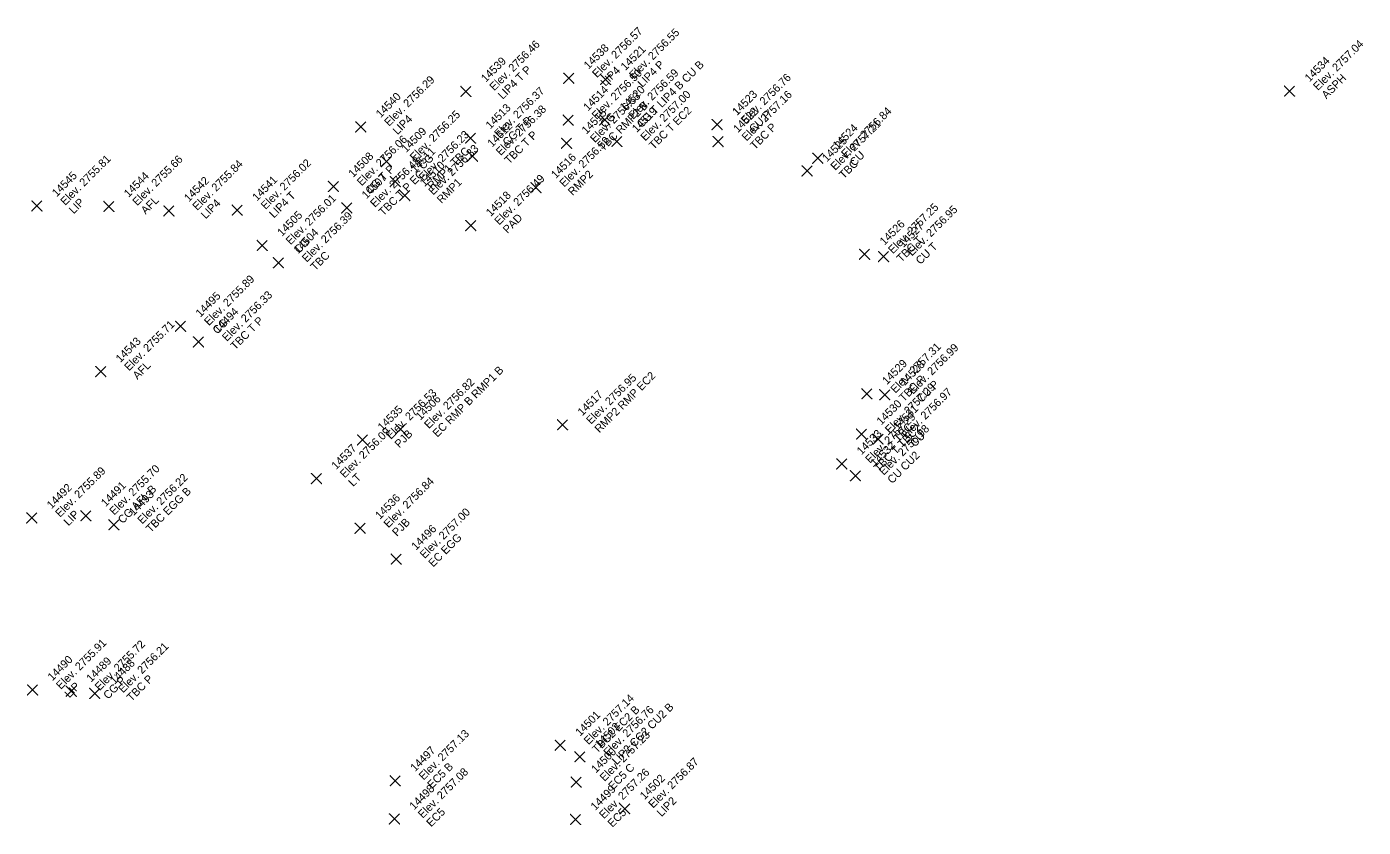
# Model space of a CAD drawing. Extents: x 2493999 to 2503109, y 700767 to 706646.
# Drawn here: x 2502322.22 to 2502362.3, y 703506.66 to 703530.66 of the extents above; entities that cross this region are included whole.
import ezdxf

# ---------------------------------------------------------------- set-up
doc = ezdxf.new("R2010")
doc.units = 0
doc.layers.add('ALG_CL_BLUE_Horiz', color=7, linetype='Continuous')
doc.layers.add('DES_SURFACE_Existing-Ground', color=7, linetype='Continuous')

msp = doc.modelspace()

# ---------------------------------------------------------------- linework, layer by layer
at = {"layer": 'ALG_CL_BLUE_Horiz'}
for points in [[(2502335.391, 703528.719), (2502335.241, 703528.869), (2502335.391, 703528.719), (2502335.241, 703528.569), (2502335.391, 703528.719), (2502335.541, 703528.569), (2502335.391, 703528.719), (2502335.541, 703528.869)], [(2502338.472, 703529.111), (2502338.322, 703529.261), (2502338.472, 703529.111), (2502338.322, 703528.961), (2502338.472, 703529.111), (2502338.622, 703528.961), (2502338.472, 703529.111), (2502338.622, 703529.261)], [(2502339.578, 703529.076), (2502339.428, 703529.226), (2502339.578, 703529.076), (2502339.428, 703528.926), (2502339.578, 703529.076), (2502339.728, 703528.926), (2502339.578, 703529.076), (2502339.728, 703529.226)], [(2502360.093, 703528.73), (2502359.943, 703528.88), (2502360.093, 703528.73), (2502359.943, 703528.58), (2502360.093, 703528.73), (2502360.243, 703528.58), (2502360.093, 703528.73), (2502360.243, 703528.88)], [(2502332.236, 703527.655), (2502332.086, 703527.805), (2502332.236, 703527.655), (2502332.086, 703527.505), (2502332.236, 703527.655), (2502332.386, 703527.505), (2502332.236, 703527.655), (2502332.386, 703527.805)], [(2502338.458, 703527.858), (2502338.308, 703528.008), (2502338.458, 703527.858), (2502338.308, 703527.708), (2502338.458, 703527.858), (2502338.608, 703527.708), (2502338.458, 703527.858), (2502338.608, 703528.008)], [(2502339.554, 703527.863), (2502339.404, 703528.013), (2502339.554, 703527.863), (2502339.404, 703527.713), (2502339.554, 703527.863), (2502339.704, 703527.713), (2502339.554, 703527.863), (2502339.704, 703528.013)], [(2502342.924, 703527.723), (2502342.774, 703527.873), (2502342.924, 703527.723), (2502342.774, 703527.573), (2502342.924, 703527.723), (2502343.074, 703527.573), (2502342.924, 703527.723), (2502343.074, 703527.873)], [(2502335.53, 703527.318), (2502335.38, 703527.468), (2502335.53, 703527.318), (2502335.38, 703527.168), (2502335.53, 703527.318), (2502335.68, 703527.168), (2502335.53, 703527.318), (2502335.68, 703527.468)], [(2502338.408, 703527.166), (2502338.258, 703527.316), (2502338.408, 703527.166), (2502338.258, 703527.016), (2502338.408, 703527.166), (2502338.558, 703527.016), (2502338.408, 703527.166), (2502338.558, 703527.316)], [(2502339.918, 703527.217), (2502339.768, 703527.367), (2502339.918, 703527.217), (2502339.768, 703527.067), (2502339.918, 703527.217), (2502340.068, 703527.067), (2502339.918, 703527.217), (2502340.068, 703527.367)], [(2502342.953, 703527.212), (2502342.803, 703527.362), (2502342.953, 703527.212), (2502342.803, 703527.062), (2502342.953, 703527.212), (2502343.103, 703527.062), (2502342.953, 703527.212), (2502343.103, 703527.362)], [(2502335.584, 703526.775), (2502335.434, 703526.925), (2502335.584, 703526.775), (2502335.434, 703526.625), (2502335.584, 703526.775), (2502335.734, 703526.625), (2502335.584, 703526.775), (2502335.734, 703526.925)], [(2502345.939, 703526.713), (2502345.789, 703526.863), (2502345.939, 703526.713), (2502345.789, 703526.563), (2502345.939, 703526.713), (2502346.089, 703526.563), (2502345.939, 703526.713), (2502346.089, 703526.863)], [(2502333.004, 703526.614), (2502332.854, 703526.764), (2502333.004, 703526.614), (2502332.854, 703526.464), (2502333.004, 703526.614), (2502333.154, 703526.464), (2502333.004, 703526.614), (2502333.154, 703526.764)], [(2502345.619, 703526.334), (2502345.469, 703526.484), (2502345.619, 703526.334), (2502345.469, 703526.184), (2502345.619, 703526.334), (2502345.769, 703526.184), (2502345.619, 703526.334), (2502345.769, 703526.484)], [(2502333.272, 703526.012), (2502333.122, 703526.162), (2502333.272, 703526.012), (2502333.122, 703525.862), (2502333.272, 703526.012), (2502333.422, 703525.862), (2502333.272, 703526.012), (2502333.422, 703526.162)], [(2502331.414, 703525.868), (2502331.264, 703526.018), (2502331.414, 703525.868), (2502331.264, 703525.718), (2502331.414, 703525.868), (2502331.564, 703525.718), (2502331.414, 703525.868), (2502331.564, 703526.018)], [(2502333.556, 703525.594), (2502333.406, 703525.744), (2502333.556, 703525.594), (2502333.406, 703525.444), (2502333.556, 703525.594), (2502333.706, 703525.444), (2502333.556, 703525.594), (2502333.706, 703525.744)], [(2502337.491, 703525.833), (2502337.341, 703525.983), (2502337.491, 703525.833), (2502337.341, 703525.683), (2502337.491, 703525.833), (2502337.641, 703525.683), (2502337.491, 703525.833), (2502337.641, 703525.983)], [(2502322.523, 703525.285), (2502322.373, 703525.435), (2502322.523, 703525.285), (2502322.373, 703525.135), (2502322.523, 703525.285), (2502322.673, 703525.135), (2502322.523, 703525.285), (2502322.673, 703525.435)], [(2502324.682, 703525.272), (2502324.532, 703525.422), (2502324.682, 703525.272), (2502324.532, 703525.122), (2502324.682, 703525.272), (2502324.832, 703525.122), (2502324.682, 703525.272), (2502324.832, 703525.422)], [(2502326.485, 703525.133), (2502326.335, 703525.283), (2502326.485, 703525.133), (2502326.335, 703524.983), (2502326.485, 703525.133), (2502326.635, 703524.983), (2502326.485, 703525.133), (2502326.635, 703525.283)], [(2502328.532, 703525.159), (2502328.382, 703525.309), (2502328.532, 703525.159), (2502328.382, 703525.009), (2502328.532, 703525.159), (2502328.682, 703525.009), (2502328.532, 703525.159), (2502328.682, 703525.309)], [(2502331.814, 703525.224), (2502331.664, 703525.374), (2502331.814, 703525.224), (2502331.664, 703525.074), (2502331.814, 703525.224), (2502331.964, 703525.074), (2502331.814, 703525.224), (2502331.964, 703525.374)], [(2502335.537, 703524.696), (2502335.387, 703524.846), (2502335.537, 703524.696), (2502335.387, 703524.546), (2502335.537, 703524.696), (2502335.687, 703524.546), (2502335.537, 703524.696), (2502335.687, 703524.846)], [(2502329.282, 703524.101), (2502329.132, 703524.251), (2502329.282, 703524.101), (2502329.132, 703523.951), (2502329.282, 703524.101), (2502329.432, 703523.951), (2502329.282, 703524.101), (2502329.432, 703524.251)], [(2502329.767, 703523.579), (2502329.617, 703523.729), (2502329.767, 703523.579), (2502329.617, 703523.429), (2502329.767, 703523.579), (2502329.917, 703523.429), (2502329.767, 703523.579), (2502329.917, 703523.729)], [(2502347.348, 703523.834), (2502347.198, 703523.984), (2502347.348, 703523.834), (2502347.198, 703523.684), (2502347.348, 703523.834), (2502347.498, 703523.684), (2502347.348, 703523.834), (2502347.498, 703523.984)], [(2502347.917, 703523.767), (2502347.767, 703523.917), (2502347.917, 703523.767), (2502347.767, 703523.617), (2502347.917, 703523.767), (2502348.067, 703523.617), (2502347.917, 703523.767), (2502348.067, 703523.917)], [(2502326.832, 703521.679), (2502326.682, 703521.829), (2502326.832, 703521.679), (2502326.682, 703521.529), (2502326.832, 703521.679), (2502326.982, 703521.529), (2502326.832, 703521.679), (2502326.982, 703521.829)], [(2502327.368, 703521.206), (2502327.218, 703521.356), (2502327.368, 703521.206), (2502327.218, 703521.056), (2502327.368, 703521.206), (2502327.518, 703521.056), (2502327.368, 703521.206), (2502327.518, 703521.356)], [(2502324.437, 703520.319), (2502324.287, 703520.469), (2502324.437, 703520.319), (2502324.287, 703520.169), (2502324.437, 703520.319), (2502324.587, 703520.169), (2502324.437, 703520.319), (2502324.587, 703520.469)], [(2502347.418, 703519.653), (2502347.268, 703519.803), (2502347.418, 703519.653), (2502347.268, 703519.503), (2502347.418, 703519.653), (2502347.568, 703519.503), (2502347.418, 703519.653), (2502347.568, 703519.803)], [(2502347.949, 703519.625), (2502347.799, 703519.775), (2502347.949, 703519.625), (2502347.799, 703519.475), (2502347.949, 703519.625), (2502348.099, 703519.475), (2502347.949, 703519.625), (2502348.099, 703519.775)], [(2502338.289, 703518.722), (2502338.139, 703518.872), (2502338.289, 703518.722), (2502338.139, 703518.572), (2502338.289, 703518.722), (2502338.439, 703518.572), (2502338.289, 703518.722), (2502338.439, 703518.872)], [(2502333.431, 703518.59), (2502333.281, 703518.74), (2502333.431, 703518.59), (2502333.281, 703518.44), (2502333.431, 703518.59), (2502333.581, 703518.44), (2502333.431, 703518.59), (2502333.581, 703518.74)], [(2502347.254, 703518.443), (2502347.104, 703518.593), (2502347.254, 703518.443), (2502347.104, 703518.293), (2502347.254, 703518.443), (2502347.404, 703518.293), (2502347.254, 703518.443), (2502347.404, 703518.593)], [(2502347.75, 703518.296), (2502347.6, 703518.446), (2502347.75, 703518.296), (2502347.6, 703518.146), (2502347.75, 703518.296), (2502347.9, 703518.146), (2502347.75, 703518.296), (2502347.9, 703518.446)], [(2502332.292, 703518.269), (2502332.142, 703518.419), (2502332.292, 703518.269), (2502332.142, 703518.119), (2502332.292, 703518.269), (2502332.442, 703518.119), (2502332.292, 703518.269), (2502332.442, 703518.419)], [(2502346.66, 703517.55), (2502346.51, 703517.7), (2502346.66, 703517.55), (2502346.51, 703517.4), (2502346.66, 703517.55), (2502346.81, 703517.4), (2502346.66, 703517.55), (2502346.81, 703517.7)], [(2502330.906, 703517.109), (2502330.756, 703517.259), (2502330.906, 703517.109), (2502330.756, 703516.959), (2502330.906, 703517.109), (2502331.056, 703516.959), (2502330.906, 703517.109), (2502331.056, 703517.259)], [(2502347.07, 703517.194), (2502346.92, 703517.344), (2502347.07, 703517.194), (2502346.92, 703517.044), (2502347.07, 703517.194), (2502347.22, 703517.044), (2502347.07, 703517.194), (2502347.22, 703517.344)], [(2502322.369, 703515.93), (2502322.219, 703516.08), (2502322.369, 703515.93), (2502322.219, 703515.78), (2502322.369, 703515.93), (2502322.519, 703515.78), (2502322.369, 703515.93), (2502322.519, 703516.08)], [(2502323.994, 703515.995), (2502323.844, 703516.145), (2502323.994, 703515.995), (2502323.844, 703515.845), (2502323.994, 703515.995), (2502324.144, 703515.845), (2502323.994, 703515.995), (2502324.144, 703516.145)], [(2502324.832, 703515.727), (2502324.682, 703515.877), (2502324.832, 703515.727), (2502324.682, 703515.577), (2502324.832, 703515.727), (2502324.982, 703515.577), (2502324.832, 703515.727), (2502324.982, 703515.877)], [(2502332.216, 703515.618), (2502332.066, 703515.768), (2502332.216, 703515.618), (2502332.066, 703515.468), (2502332.216, 703515.618), (2502332.366, 703515.468), (2502332.216, 703515.618), (2502332.366, 703515.768)], [(2502333.302, 703514.695), (2502333.152, 703514.845), (2502333.302, 703514.695), (2502333.152, 703514.545), (2502333.302, 703514.695), (2502333.452, 703514.545), (2502333.302, 703514.695), (2502333.452, 703514.845)], [(2502322.393, 703510.774), (2502322.243, 703510.924), (2502322.393, 703510.774), (2502322.243, 703510.624), (2502322.393, 703510.774), (2502322.543, 703510.624), (2502322.393, 703510.774), (2502322.543, 703510.924)], [(2502323.555, 703510.732), (2502323.405, 703510.882), (2502323.555, 703510.732), (2502323.405, 703510.582), (2502323.555, 703510.732), (2502323.705, 703510.582), (2502323.555, 703510.732), (2502323.705, 703510.882)], [(2502324.259, 703510.669), (2502324.109, 703510.819), (2502324.259, 703510.669), (2502324.109, 703510.519), (2502324.259, 703510.669), (2502324.409, 703510.519), (2502324.259, 703510.669), (2502324.409, 703510.819)], [(2502338.218, 703509.115), (2502338.068, 703509.265), (2502338.218, 703509.115), (2502338.068, 703508.965), (2502338.218, 703509.115), (2502338.368, 703508.965), (2502338.218, 703509.115), (2502338.368, 703509.265)], [(2502338.809, 703508.767), (2502338.659, 703508.917), (2502338.809, 703508.767), (2502338.659, 703508.617), (2502338.809, 703508.767), (2502338.959, 703508.617), (2502338.809, 703508.767), (2502338.959, 703508.917)], [(2502333.271, 703508.051), (2502333.121, 703508.201), (2502333.271, 703508.051), (2502333.121, 703507.901), (2502333.271, 703508.051), (2502333.421, 703507.901), (2502333.271, 703508.051), (2502333.421, 703508.201)], [(2502338.697, 703508.012), (2502338.547, 703508.162), (2502338.697, 703508.012), (2502338.547, 703507.862), (2502338.697, 703508.012), (2502338.847, 703507.862), (2502338.697, 703508.012), (2502338.847, 703508.162)], [(2502340.155, 703507.21), (2502340.005, 703507.36), (2502340.155, 703507.21), (2502340.005, 703507.06), (2502340.155, 703507.21), (2502340.305, 703507.06), (2502340.155, 703507.21), (2502340.305, 703507.36)], [(2502333.245, 703506.905), (2502333.095, 703507.055), (2502333.245, 703506.905), (2502333.095, 703506.755), (2502333.245, 703506.905), (2502333.395, 703506.755), (2502333.245, 703506.905), (2502333.395, 703507.055)], [(2502338.679, 703506.891), (2502338.529, 703507.041), (2502338.679, 703506.891), (2502338.529, 703506.741), (2502338.679, 703506.891), (2502338.829, 703506.741), (2502338.679, 703506.891), (2502338.829, 703507.041)]]:
    msp.add_lwpolyline(points, dxfattribs=at)

# ---------------------------------------------------------------- texts
at = {"layer": 'DES_SURFACE_Existing-Ground'}
for s, p in [('Elev. 2756.57', (2502339.321, 703529.111)), ('Elev. 2756.55', (2502340.427, 703529.076)), ('Elev. 2756.46', (2502336.24, 703528.719)), ('14538', (2502339.066, 703529.366)), ('14521', (2502340.172, 703529.331)), ('Elev. 2757.04', (2502360.942, 703528.73)), ('14539', (2502335.985, 703528.974)), ('14534', (2502360.687, 703528.985)), ('LIP4 T P', (2502336.494, 703528.464)), ('Elev. 2756.50', (2502339.307, 703527.858)), ('LIP4', (2502339.575, 703528.856)), ('Elev. 2756.59', (2502340.403, 703527.863)), ('LIP4 P', (2502340.681, 703528.821)), ('CG T LIP4 B CU B', (2502340.657, 703527.608)), ('Elev. 2756.29', (2502333.085, 703527.655)), ('Elev. 2756.37', (2502336.379, 703527.318)), ('14514', (2502339.052, 703528.113)), ('14520', (2502340.148, 703528.118)), ('Elev. 2756.76', (2502343.773, 703527.723)), ('ASPH', (2502361.196, 703528.475)), ('14540', (2502332.83, 703527.91)), ('Elev. 2756.53', (2502339.257, 703527.166)), ('Elev. 2757.00', (2502340.767, 703527.217)), ('14523', (2502343.518, 703527.978)), ('Elev. 2757.16', (2502343.802, 703527.212)), ('Elev. 2756.25', (2502333.853, 703526.614)), ('14513', (2502336.124, 703527.573)), ('Elev. 2756.38', (2502336.433, 703526.775)), ('14515', (2502339.002, 703527.421)), ('TBC RMP2 B', (2502339.511, 703526.911)), ('CG', (2502339.561, 703527.603)), ('14519', (2502340.512, 703527.472)), ('TBC T EC2', (2502341.021, 703526.962)), ('14522', (2502343.547, 703527.467)), ('CU P', (2502344.027, 703527.468)), ('Elev. 2756.84', (2502346.788, 703526.713)), ('LIP4', (2502333.339, 703527.4)), ('14512', (2502336.178, 703527.03)), ('CG T P', (2502336.633, 703527.063)), ('TBC P', (2502344.056, 703526.957)), ('Elev. 2757.21', (2502346.468, 703526.334)), ('14524', (2502346.533, 703526.968)), ('Elev. 2756.06', (2502332.263, 703525.868)), ('14509', (2502333.598, 703526.869)), ('Elev. 2756.23', (2502334.121, 703526.012)), ('TBC T P', (2502336.687, 703526.52)), ('Elev. 2756.52', (2502338.34, 703525.833)), ('14525', (2502346.213, 703526.589)), ('14508', (2502332.008, 703526.123)), ('14511', (2502333.866, 703526.267)), ('RMP1 TBC', (2502334.375, 703525.757)), ('Elev. 2756.33', (2502334.405, 703525.594)), ('14516', (2502338.085, 703526.088)), ('CU', (2502347.042, 703526.458)), ('Elev. 2755.81', (2502323.372, 703525.285)), ('Elev. 2755.66', (2502325.531, 703525.272)), ('Elev. 2755.84', (2502327.334, 703525.133)), ('Elev. 2756.02', (2502329.381, 703525.159)), ('CG T P', (2502332.517, 703525.613)), ('Elev. 2756.48', (2502332.663, 703525.224)), ('CG', (2502334.107, 703526.359)), ('14510', (2502334.15, 703525.849)), ('TBC', (2502346.722, 703526.079)), ('14545', (2502323.117, 703525.54)), ('14544', (2502325.276, 703525.527)), ('14542', (2502327.079, 703525.388)), ('14541', (2502329.126, 703525.414)), ('14507', (2502332.408, 703525.479)), ('TBC T P EC', (2502332.917, 703524.969)), ('RMP1', (2502334.659, 703525.339)), ('Elev. 2756.49', (2502336.386, 703524.696)), ('RMP2', (2502338.594, 703525.578)), ('LIP4 T', (2502329.635, 703524.904)), ('14518', (2502336.131, 703524.951)), ('LIP', (2502323.626, 703525.03)), ('AFL', (2502325.785, 703525.017)), ('LIP4', (2502327.588, 703524.878)), ('Elev. 2756.01', (2502330.131, 703524.101)), ('Elev. 2757.25', (2502348.197, 703523.834)), ('Elev. 2756.95', (2502348.766, 703523.767)), ('14505', (2502329.876, 703524.356)), ('Elev. 2756.39', (2502330.616, 703523.579)), ('PAD', (2502336.64, 703524.441)), ('14526', (2502347.942, 703524.089)), ('14504', (2502330.361, 703523.834)), ('14527', (2502348.511, 703524.022)), ('CG', (2502330.385, 703523.846)), ('TBC T', (2502348.451, 703523.579)), ('CU T', (2502349.02, 703523.512)), ('TBC', (2502330.87, 703523.324)), ('Elev. 2755.89', (2502327.681, 703521.679)), ('14495', (2502327.426, 703521.934)), ('Elev. 2756.33', (2502328.217, 703521.206)), ('14494', (2502327.962, 703521.461)), ('Elev. 2755.71', (2502325.286, 703520.319)), ('CG', (2502327.935, 703521.424)), ('TBC T P', (2502328.471, 703520.951)), ('14543', (2502325.031, 703520.574)), ('Elev. 2757.31', (2502348.267, 703519.653)), ('Elev. 2756.99', (2502348.798, 703519.625)), ('AFL', (2502325.54, 703520.064)), ('EC RMP B RMP1 B', (2502334.534, 703518.335)), ('14529', (2502348.012, 703519.908)), ('14528', (2502348.543, 703519.88)), ('Elev. 2756.82', (2502334.28, 703518.59)), ('Elev. 2756.95', (2502339.138, 703518.722)), ('RMP2 RMP EC2', (2502339.392, 703518.467)), ('TBC P', (2502348.521, 703519.398)), ('CU P', (2502349.052, 703519.37)), ('Elev. 2756.53', (2502333.141, 703518.269)), ('14517', (2502338.883, 703518.977)), ('Elev. 2757.29', (2502348.103, 703518.443)), ('Elev. 2756.97', (2502348.599, 703518.296)), ('14535', (2502332.886, 703518.524)), ('14506', (2502334.025, 703518.845)), ('14530', (2502347.848, 703518.698)), ('14531', (2502348.344, 703518.551)), ('Elev. 2757.29', (2502347.509, 703517.55)), ('Elev. 2756.09', (2502331.755, 703517.109)), ('PJB', (2502333.395, 703518.014)), ('14533', (2502347.254, 703517.805)), ('TBC T TBC2', (2502347.763, 703517.295)), ('Elev. 2756.98', (2502347.919, 703517.194)), ('TBC', (2502348.357, 703518.188)), ('CU', (2502348.853, 703518.041)), ('14537', (2502331.5, 703517.364)), ('14532', (2502347.664, 703517.449)), ('CU CU2', (2502348.173, 703516.939)), ('Elev. 2755.89', (2502323.218, 703515.93)), ('Elev. 2755.70', (2502324.843, 703515.995)), ('Elev. 2756.22', (2502325.681, 703515.727)), ('LT', (2502332.009, 703516.854)), ('14492', (2502322.963, 703516.185)), ('14491', (2502324.588, 703516.25)), ('CG AFL B', (2502325.097, 703515.74)), ('TBC EGG B', (2502325.935, 703515.472)), ('Elev. 2756.84', (2502333.065, 703515.618)), ('14493', (2502325.426, 703515.982)), ('14536', (2502332.81, 703515.873)), ('LIP', (2502323.472, 703515.675)), ('Elev. 2757.00', (2502334.151, 703514.695)), ('PJB', (2502333.319, 703515.363)), ('14496', (2502333.896, 703514.95)), ('EC EGG', (2502334.405, 703514.44)), ('Elev. 2755.91', (2502323.242, 703510.774)), ('Elev. 2755.72', (2502324.404, 703510.732)), ('Elev. 2756.21', (2502325.108, 703510.669)), ('14490', (2502322.987, 703511.029)), ('14489', (2502324.149, 703510.987)), ('14488', (2502324.853, 703510.924)), ('LIP', (2502323.496, 703510.519)), ('CG P', (2502324.658, 703510.477)), ('TBC P', (2502325.362, 703510.414)), ('Elev. 2757.14', (2502339.067, 703509.115)), ('14501', (2502338.812, 703509.37)), ('TBC2 EC2 B', (2502339.321, 703508.86)), ('Elev. 2756.76', (2502339.658, 703508.767)), ('LIP2 CG2 CU2 B', (2502339.912, 703508.512)), ('14503', (2502339.403, 703509.022)), ('Elev. 2757.13', (2502334.12, 703508.051)), ('Elev. 2757.23', (2502339.546, 703508.012)), ('14497', (2502333.865, 703508.306)), ('14500', (2502339.291, 703508.267)), ('Elev. 2757.08', (2502334.094, 703506.905)), ('EC5 B', (2502334.374, 703507.796)), ('Elev. 2757.26', (2502339.528, 703506.891)), ('EC5 C', (2502339.8, 703507.757)), ('Elev. 2756.87', (2502341.004, 703507.21)), ('14502', (2502340.749, 703507.465)), ('14498', (2502333.839, 703507.16)), ('14499', (2502339.273, 703507.146)), ('EC5', (2502334.348, 703506.65)), ('EC5', (2502339.782, 703506.636)), ('LIP2', (2502341.258, 703506.955))]:
    msp.add_text(s, height=0.24, rotation=45, dxfattribs=at).set_placement(p)

doc.saveas('drawing.dxf')
